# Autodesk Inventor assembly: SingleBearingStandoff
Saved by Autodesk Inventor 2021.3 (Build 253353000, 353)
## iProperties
Created: 2023-01
Part Number: SingleBearingStandoff
Document SubType Name: Assembly
Designer: AdminForWorker
Title: SingleBearingStandoff
Author: AdminForWorker
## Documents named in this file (3)
- c:\worker\convert-fusion-r07-cosv3\tmp\job-1\43\output\files\ace6bc6a-1a7f-4a13-90af-7ecc996d3367\SingleBearingStandoff.iam
- c:\worker\convert-fusion-r07-cosv3\tmp\job-1\43\output\files\ace6bc6a-1a7f-4a13-90af-7ecc996d3367\Washer.ipt
- c:\worker\convert-fusion-r07-cosv3\tmp\job-1\43\output\files\ace6bc6a-1a7f-4a13-90af-7ecc996d3367\Part8.ipt
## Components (2 placed, 2 different names)
1. Washer:1
2. Part8
